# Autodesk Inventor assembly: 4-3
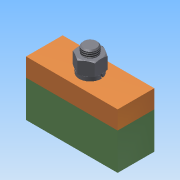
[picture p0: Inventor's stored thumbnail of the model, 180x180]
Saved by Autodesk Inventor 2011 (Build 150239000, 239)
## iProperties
Created: 2014-03
Part Number: 4-3
Document SubType Name: Assembly
Designer: Administrator
Author: Administrator
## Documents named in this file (6)
- C:\Documents and Settings\Administrator\桌面\模型\4-3.iam
- C:\Documents and Settings\Administrator\桌面\模型\4-3b.ipt
- C:\Documents and Settings\Administrator\桌面\模型\4-3a.ipt
- C:\Documents and Settings\Administrator\桌面\模型\螺柱 GB 897 A M16 x 40.ipt
- C:\Documents and Settings\Administrator\桌面\模型\螺母 GB_T 6170 M16.ipt
- C:\Documents and Settings\Administrator\桌面\模型\垫圈 GB 93-87 16.ipt
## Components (5 placed, 5 different names)
1. 4-3b:1 — 配合:1, 表面齐平:1, 配合:2
2. 4-3a:1 — 配合:1, 表面齐平:1, 配合:2, 配合:3, 插入:1
3. 螺柱 GB 897 A M16 x 40:1 — 配合:3
4. 螺母 GB_T 6170 M16:1 — 插入:2
5. 垫圈 GB 93-87 16:1 — 插入:1, 插入:2
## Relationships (6: Mate 3, Insert 2, Flush 1)
- 配合:1 [Mate]: 4-3b:1 ↔ 4-3a:1
- 表面齐平:1 [Flush]: 4-3b:1 ↔ 4-3a:1
- 配合:2 [Mate]: 4-3b:1 ↔ 4-3a:1
- 配合:3 [Mate]: 4-3a:1 ↔ 螺柱 GB 897 A M16 x 40:1
- 插入:1 [Insert]: 4-3a:1 ↔ 垫圈 GB 93-87 16:1
- 插入:2 [Insert]: 螺母 GB_T 6170 M16:1 ↔ 垫圈 GB 93-87 16:1
